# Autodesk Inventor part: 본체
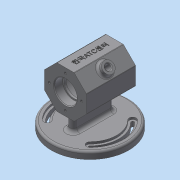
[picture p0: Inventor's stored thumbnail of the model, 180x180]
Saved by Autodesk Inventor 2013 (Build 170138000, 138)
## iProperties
Created: 2017-06
Part Number: 본체
Material: 일반
Document SubType Name: Modeling
Designer: Administrator
Density: 1 g/cm^3
Author: Administrator
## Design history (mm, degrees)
sketch "스케치1"
  geometry: 1 further point
sketch "스케치2"
  geometry: C1 r 55 at (0, 0); 1 further point
  constraints: 1 centre point, 1 coincident
  dimensions: "d0" = 110 diameter of C1
extrude "돌출1" new body sketch "스케치2" distance "d2" = 10; taper "d3" = 0 deg
sketch "스케치3" dims "d4" = 60
  geometry: L1 (-55, 0)-(55, 0) reference; L2 (-30, 74.426)-(-12.426, 92); L3 (-12.426, 92)-(12.426, 92); L4 (12.426, 92)-(30, 74.426); L5 (30, 74.426)-(30, 49.574); L6 (30, 49.574)-(12.426, 32); L7 (12.426, 32)-(-12.426, 32); L8 (-12.426, 32)-(-30, 49.574); L9 (-30, 49.574)-(-30, 74.426); 4 further points
  constraints: 16 end point, 2 horizontal alignment, 1 coincident, 1 midpoint, 1 vertical alignment, 19 other
  dimensions: "d6" = 62 distance from line of L1 point (0, 62)
extrude "돌출2" join sketch "스케치3" stored distance "d7" = 70; taper "d8" = 0 deg
sketch "스케치4"
  geometry: L1 (-55, 0)-(55, 0) reference; C1 r 16 at (0, 62); 1 further point
  constraints: 1 centre point, 1 vertical alignment
  dimensions: "d9" = 62 distance from line of L1 C1.centre; "d10" = 32 diameter of C1
extrude "돌출3" cut sketch "스케치4" distance "d11" = 12; taper "d12" = 0 deg
sketch "스케치5"
  geometry: C1 r 16 at (0, 0) reference; C2 r 14 at (0, 0); 1 further point
  constraints: 1 centre point, 1 coincident
  dimensions: "d13" = 28 diameter of C2
extrude "돌출4" cut sketch "스케치5" distance "d15" = 3; taper "d16" = 0 deg
sketch "스케치6"
  geometry: C1 r 14 at (0, 0) reference; C2 r 25 at (0, 0); 1 further point
  constraints: 1 centre point, 1 coincident
  dimensions: "d17" = 50 diameter of C2
extrude "돌출5" cut sketch "스케치6" distance "d19" = 40; taper "d20" = 0 deg
sketch "스케치7"
  geometry: L1 (55, 0)-(-55, 0) reference; C1 r 16 at (0, -62); 2 further points
  constraints: 1 centre point, 1 midpoint, 1 vertical alignment
  dimensions: "d21" = 62 distance from line of L1 C1.centre; "d22" = 32 diameter of C1
extrude "돌출6" cut sketch "스케치7" distance "d23" = 12; taper "d24" = 0 deg
sketch "스케치8"
  geometry: C1 r 16 at (0, 0) reference; C2 r 14 at (0, 0); 1 further point
  constraints: 1 centre point, 1 coincident
  dimensions: "d25" = 28 diameter of C2
extrude "돌출7" cut sketch "스케치8" distance "d27" = 3; taper "d28" = 0 deg
fillet "모깎기1" dims "d29" = 0.3
fillet "모깎기2" dims "d30" = 3
chamfer "모따기1" distance "d31" = 1; stored, may be unused: second distance "d32" = 2, angle "d33" = 45 deg
sketch "스케치9"
  geometry: L1 (-5, 24)-(-5, -24); L2 (5, 24)-(5, -24); C1 r 55 at (0, 0) reference; A1 r 5 centre (0, 24) between (5, 24) and (-5, 24); A2 r 5 centre (0, -24) between (-5, -24) and (5, -24)
  constraints: 4 end point, 4 point on circle, 2 centre point, 2 tangent, 2 vertical alignment, 1 equal radius, 1 parallel, 1 vertical
  dimensions: "d34" = 5 radius of A1; "d36" = 48 distance of A2.centre A1.centre; "d37" = 24 distance of C1.centre A2.centre
extrude "돌출8" join sketch "스케치9" stored distance "d38" = 3; taper "d39" = 0 deg
fillet "모깎기3" dims "d40" = 5
fillet "모깎기4" dims "d41" = 1
sketch "스케치10"
  geometry: C1 r 17 at (0, 62) reference; 5 further points
  constraints: 1 vertical alignment, 5 other
  dimensions: "d42" = 23 distance of C1.centre point (0, 85); "d45" = 360 deg dimension on C1.centre point (0, 85) (derived)
hole "구멍1" sketch "스케치10" at (0, 85), (23, 62), (0, 39), (-23, 62) diameter "d47" = 3.242; stored, may be unused: countersink angle "d51" = 90 deg, drill point angle "d53" = 118 deg; dims "d48" = 8, "d49" = 4, "d50" = 2, "d52" = 10
sketch "스케치11"
  geometry: C1 r 17 at (0, -62) reference; 5 further points
  constraints: 1 vertical alignment, 5 other
  dimensions: "d54" = 23 distance of C1.centre point (0, -39); "d57" = 360 deg dimension on C1.centre point (0, -39) (derived)
hole "구멍2" sketch "스케치11" at (0, -85), (23, -62), (0, -39), (-23, -62) diameter "d59" = 3.242; stored, may be unused: countersink angle "d63" = 90 deg, drill point angle "d65" = 118 deg; dims "d60" = 8, "d61" = 4, "d62" = 2, "d64" = 10
fillet "모깎기5" dims "d66" = 3
sketch "스케치12"
  geometry: L1 (10, -24)-(10, 24) reference; L2 (-30.406, -30.406)-(30.406, 30.406); L3 (0, 0)-(-52, 0); A1 r 5 centre (-30.406, -30.406) between (-33.941, -33.941) and (-26.87, -26.87); A2 r 2 centre (-30.406, -30.406) between (-31.82, -31.82) and (-28.991, -28.991); A3 r 5 centre (-30.406, 30.406) between (-26.87, 26.87) and (-33.941, 33.941); A4 r 2 centre (-30.406, 30.406) between (-28.991, 28.991) and (-31.82, 31.82); A5 r 5 centre (30.406, 30.406) between (33.941, 33.941) and (26.87, 26.87); A6 r 2 centre (30.406, 30.406) between (31.82, 31.82) and (28.991, 28.991); A7 r 5 centre (30.406, -30.406) between (26.87, -26.87) and (33.941, -33.941); A8 r 2 centre (30.406, -30.406) between (28.991, -28.991) and (31.82, -31.82); A9 r 48 centre (0, 0) between (33.941, -33.941) and (33.941, 33.941); A10 r 48 centre (0, 0) between (-33.941, 33.941) and (-33.941, -33.941); A11 r 43 centre (0, 0) between (26.67, -33.73) and (26.67, 33.73); A12 r 43 centre (0, 0) between (-26.67, 33.73) and (-26.67, -33.73); A13 r 38 centre (0, 0) between (26.87, -26.87) and (26.87, 26.87); A14 r 38 centre (0, 0) between (-26.87, 26.87) and (-26.87, -26.87); A15 r 45 centre (0, 0) between (31.82, -31.82) and (31.82, 31.82); A16 r 45 centre (0, 0) between (-31.82, 31.82) and (-31.82, -31.82); A17 r 41 centre (0, 0) between (28.991, -28.991) and (28.991, 28.991); A18 r 41 centre (0, 0) between (-28.991, 28.991) and (-28.991, -28.991); 1 further point
  constraints: 45 point on circle, 18 centre point, 10 equal radius, 9 coincident, 4 end point, 4 point on line, 3 horizontal alignment, 2 vertical alignment, 1 perpendicular, 1 other
  dimensions: "d71" = 45 deg angle of L3 L2; "d72" = 38 radius of A14; "d74" = 43 radius of A12; "d75" = 48 radius of A10; "d76" = 4 diameter of A2; "d77" = 45 radius of A16
extrude "돌출9" cut sketch "스케치12" distance "d78" = 3; taper "d79" = 0 deg
sketch "스케치13"
  geometry: A1 r 41 centre (0, 0) between (-28.991, 28.991) and (-28.991, -28.991) reference; A2 r 2 centre (-30.406, 30.406) between (-28.991, 28.991) and (-31.82, 31.82) reference; A3 r 45 centre (0, 0) between (-31.82, 31.82) and (-31.82, -31.82) reference; A4 r 2 centre (-30.406, -30.406) between (-31.82, -31.82) and (-28.991, -28.991) reference; A5 r 45 centre (0, 0) between (31.82, -31.82) and (31.82, 31.82) reference; A6 r 2 centre (30.406, 30.406) between (31.82, 31.82) and (28.991, 28.991) reference; A7 r 41 centre (0, 0) between (28.991, -28.991) and (28.991, 28.991) reference; A8 r 2 centre (30.406, -30.406) between (28.991, -28.991) and (31.82, -31.82) reference
extrude "돌출10" cut sketch "스케치13" stored distance "d80" = 3; taper "d81" = 0 deg
node "작업 평면1"
sketch "스케치14"
  geometry: L1 (8.975, -59.31)-(8.975, -10.69); L2 (8.975, -10.69)-(15.635, -10.69); L3 (15.635, -10.69)-(15.635, -59.31); L4 (15.635, -59.31)-(8.975, -59.31); L5 (12.305, -59.31)-(12.305, -10.69); L6 (8.975, -35)-(15.635, -35); L7 (-17.695, -70)-(-17.695, 0) reference; L8 (-0.707, -70)-(-17.695, -70) reference; 1 further point
  constraints: 4 end point, 4 midpoint, 1 perpendicular, 2 other
  dimensions: "d83" = 30 distance between parallel lines of L7 L5; "d84" = 35 distance between parallel lines of L8 L6
feature "엠보싱1" sketch "스케치14" dims "d85" = 0.5, "d86" = 0
sketch "스케치15"
  geometry: L1 (0, 70)-(24.024, 70) reference; C1 r 8 at (12.012, 35); 2 further points
  constraints: 1 centre point, 1 horizontal alignment, 1 midpoint, 1 vertical alignment
  dimensions: "d87" = 16 diameter of C1
extrude "돌출11" join sketch "스케치15" distance "d90" = 7; taper "d91" = 0 deg
fillet "모깎기6" dims "d92" = 3
sketch "스케치16"
  geometry: C1 r 8 at (0, 0) reference; C2 r 4 at (0, 0); 1 further point
  constraints: 1 centre point, 1 coincident
  dimensions: "d93" = 8 diameter of C2
extrude "돌출12" cut sketch "스케치16" stored distance "d95" = 7; taper "d96" = 0 deg
chamfer "모따기2" distance "d97" = 1; stored, may be unused: second distance "d98" = 2, angle "d99" = 45 deg
node "솔리드1"
node "투영된 루프1"
other parameters: "d67" = 76, "d69" = 86, "d70" = 96, "d82" = 8.5
